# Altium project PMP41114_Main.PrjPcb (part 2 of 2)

## Sheet PMP41114_MAIN_LLC.SchDoc: LLC Power Stage
size A2; Date: Not shown in title block; ApprovedBy: Not shown in title block; CheckedBy: Not shown in title block; Author: Not shown in title block; CompanyName: Not shown in title block; DrawnBy: Desheng Guo; Engineer: Not shown in title block; Organization: Not shown in title block; Address1: Not shown in title block; Address2: Not shown in title block; Address3: Not shown in title block; Address4: Not shown in title block; DocumentNumber: 1; Revision: Use project parameter SCH_Rev; SheetNumber: 3; SheetTotal: 3; PageSetup: Record=PageOptions¦CenterHorizontal=True¦CenterVertical=True¦PrintScale=0.69¦XCorrection=1.00¦YCorrection=1.00¦PrintKind=0¦BorderSize=5000000¦LeftOffset=0¦BottomOffset=0¦Orientation=2¦PaperLength=1000¦PaperWidth=1000¦Scale=100¦PaperSource=15¦PrintQuality=600¦MediaType=1¦DitherType=10¦PaperKind=Letter¦PrintScaleMode=1
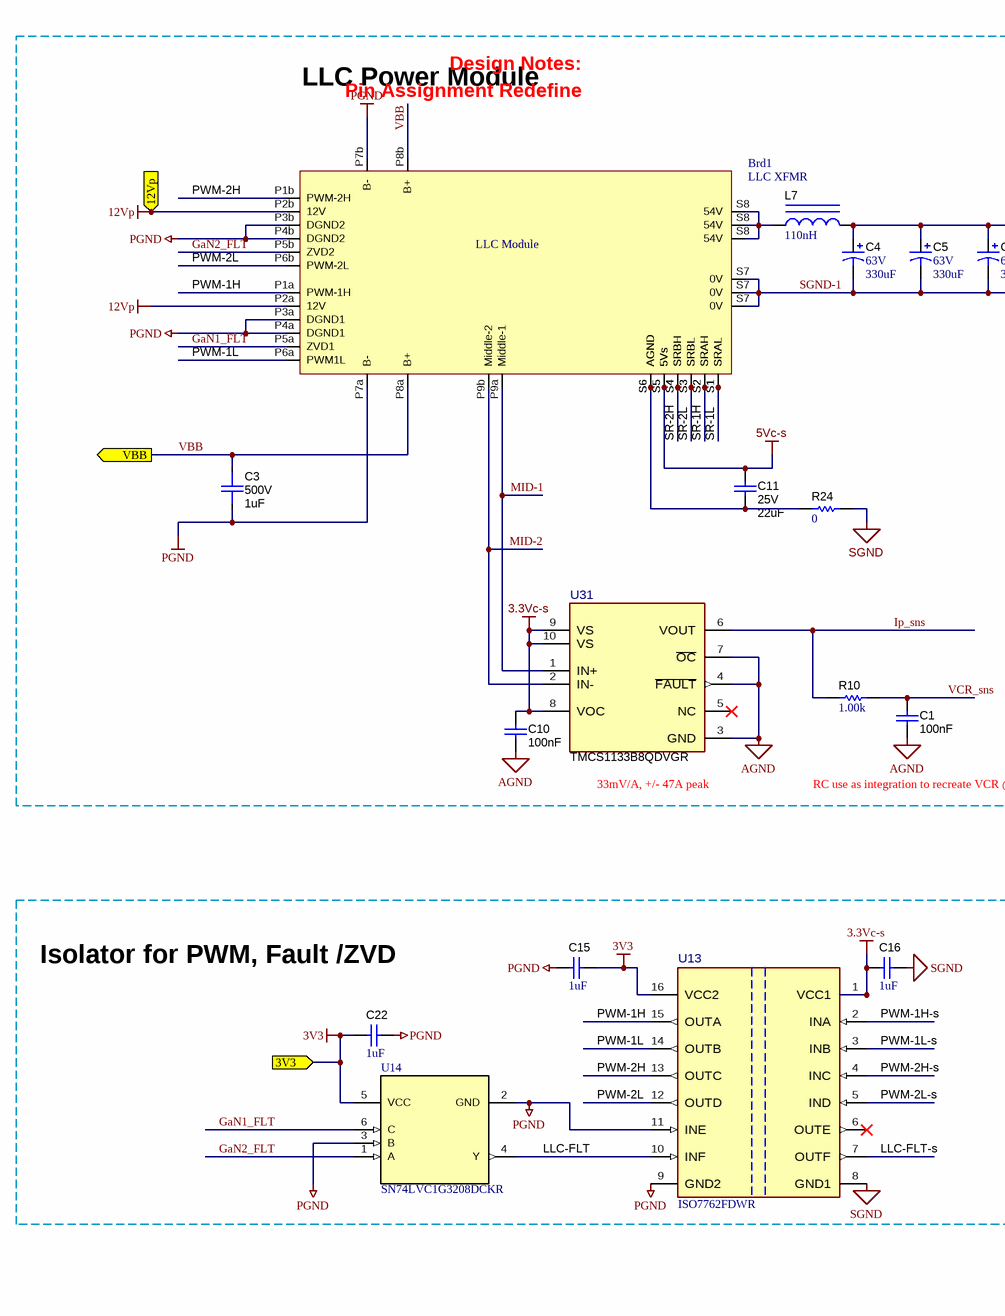
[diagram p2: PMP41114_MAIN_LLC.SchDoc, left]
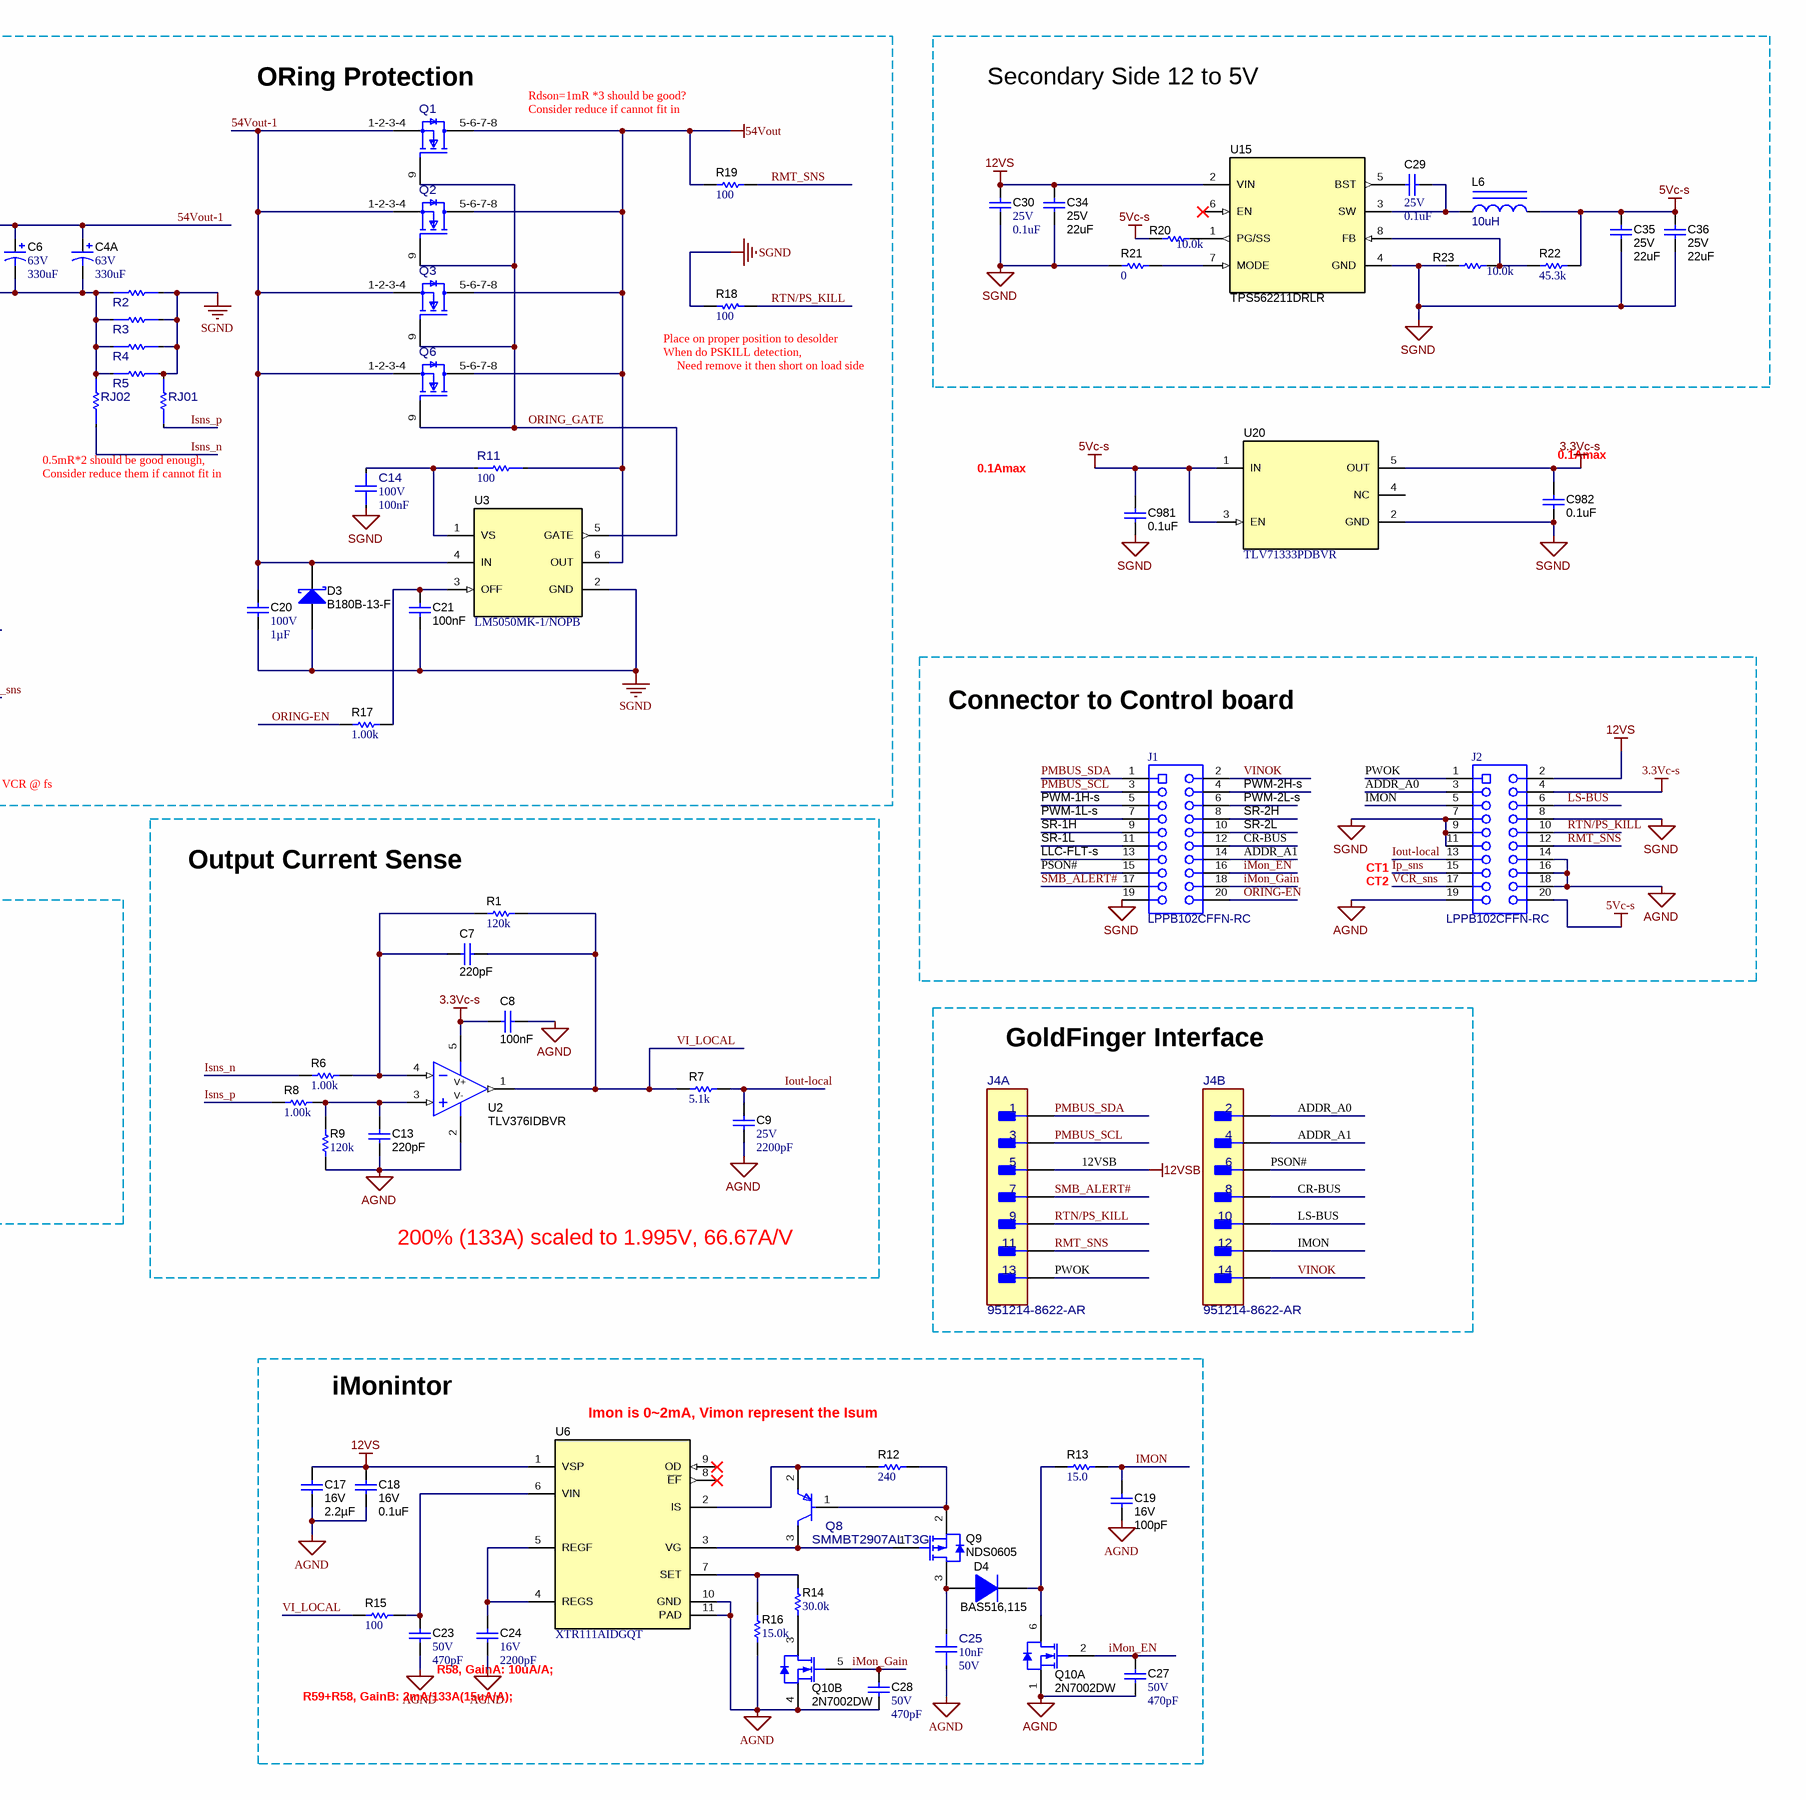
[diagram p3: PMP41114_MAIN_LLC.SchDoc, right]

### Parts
Brd1  LLC XFMR  [XFMR-PMP41114]
C1  Cap_F: 100nF  [0603]  (hidden comment: GRM188R71E104KA01D)
C3  VDC_V: 500V  ValueDisplayed: 1uF  [FP-B58031U5105M062_SMD2-MFG]  (hidden comment: B58031U5105M062)
C4  VDC_V: 63V  ValueDisplayed: 330uF  [KYB_1000x2500]  (hidden comment: EKYB630ELL331MJ25S)
C4A  VDC_V: 63V  ValueDisplayed: 330uF  [KYB_1000x2500]  (hidden comment: EKYB630ELL331MJ25S)
C5  VDC_V: 63V  ValueDisplayed: 330uF  [KYB_1000x2500]  (hidden comment: EKYB630ELL331MJ25S)
C6  VDC_V: 63V  ValueDisplayed: 330uF  [KYB_1000x2500]  (hidden comment: EKYB630ELL331MJ25S)
C7  ValueDisplayed: 220pF  [0603]  (hidden comment: GRM1885C1H221JA01D)
C8  Cap_F: 100nF  [0603]  (hidden comment: GRM188R71E104KA01D)
C9  VDC_V: 25V  ValueDisplayed: 2200pF  [0402]  (hidden comment: GRM155R71E222KA01D)
C10  Cap_F: 100nF  [0603]  (hidden comment: GRM188R71E104KA01D)
C11  VDC_V: 25V  ValueDisplayed: 22uF  [0805_HV]  (hidden comment: GRM21BR61E226ME44L)
C13  ValueDisplayed: 220pF  [0603]  (hidden comment: GRM1885C1H221JA01D)
C14  VDC_V: 100V  Cap_F: 100nF  [FP-885012206120_0603-MFG]  (hidden comment: 885012206120)
C15  ValueDisplayed: 1uF  [0402]  (hidden comment: GRM155R61A105KE15D)
C16  ValueDisplayed: 1uF  [0402]  (hidden comment: GRM155R61A105KE15D)
C17  VDC_V: 16V  Cap_F: 2.2µF  [0603]  (hidden comment: GRM188Z71C225KE43)
C18  VDC_V: 16V  ValueDisplayed: 0.1uF  [0402]  (hidden comment: GRM155R71C104KA88D)
C19  VDC_V: 16V  ValueDisplayed: 100pF  [0402]  (hidden comment: 0402YC101KAT2A)
C20  VDC_V: 100V  Cap_F: 1µF  [0805_150]  (hidden comment: KAF21KR72A105KU)
C21  Cap_F: 100nF  [0603]  (hidden comment: GRM188R71E104KA01D)
C22  ValueDisplayed: 1uF  [0402]  (hidden comment: GRM155R61A105KE15D)
C23  VDC_V: 50V  ValueDisplayed: 470pF  [0402]  (hidden comment: GRM155R71H471KA01D)
C24  VDC_V: 16V  ValueDisplayed: 2200pF  [0402]  (hidden comment: 885012205027)
C25  Cap_F: 10nF  VDC_V: 50V  [FP-C0603C103J5RAC7867_0603-MFG]  (hidden comment: C0603C103J5RAC7867)
C27  VDC_V: 50V  ValueDisplayed: 470pF  [0402]  (hidden comment: GRM155R71H471KA01D)
C28  VDC_V: 50V  ValueDisplayed: 470pF  [0402]  (hidden comment: GRM155R71H471KA01D)
C29  VDC_V: 25V  ValueDisplayed: 0.1uF  [0402]  (hidden comment: GRM155R71E104KE14D)
C30  VDC_V: 25V  ValueDisplayed: 0.1uF  [0402]  (hidden comment: GRM155R71E104KE14D)
C34  VDC_V: 25V  ValueDisplayed: 22uF  [0805_HV]  (hidden comment: GRM21BR61E226ME44L)
C35  VDC_V: 25V  ValueDisplayed: 22uF  [0805_HV]  (hidden comment: GRM21BR61E226ME44L)
C36  VDC_V: 25V  ValueDisplayed: 22uF  [0805_HV]  (hidden comment: GRM21BR61E226ME44L)
C981  ValueDisplayed: 0.1uF  [0402]  (hidden comment: GRM155R70J104KA01D)
C982  ValueDisplayed: 0.1uF  [0402]  (hidden comment: GRM155R70J104KA01D)
D3  B180B-13-F  [SMB]
D4  BAS516,115  [SOD-523]
J1  LPPB102CFFN-RC  [Sullins_LPPB102CFFN]
J2  LPPB102CFFN-RC  [Sullins_LPPB102CFFN]
J4  951214-8622-AR  [FP-951214-8622-AR_HDR14-MFG]  (parts A,B of 2)
L6  ValueDisplayed: 10uH  [VLS252010HBX]  (hidden comment: 74438323100)
L7  ValueDisplayed: 110nH  [SLC1480]  (hidden comment: SLC1480-111MLB)
Q1  IQD016N08NM5CGATMA1  [FP-IQD016N08NM5CGATMA1_TTFN-9-MFG]  (value not drawn)
Q2  IQD016N08NM5CGATMA1  [FP-IQD016N08NM5CGATMA1_TTFN-9-MFG]  (value not drawn)
Q3  IQD016N08NM5CGATMA1  [FP-IQD016N08NM5CGATMA1_TTFN-9-MFG]  (value not drawn)
Q6  IQD016N08NM5CGATMA1  [FP-IQD016N08NM5CGATMA1_TTFN-9-MFG]  (value not drawn)
Q8  SMMBT2907ALT3G  [FP-SMMBT2907ALT3G_SOT23-MFG]
Q9  NDS0605  [SOT-23]
Q10  2N7002DW  [SOT-363]  (parts A,B of 2)
R1  ValueDisplayed: 120k  [0402]  (hidden comment: CRCW0402120KFKED)
R2  CSS2H-2512R-L500F  [FP-CSS2H-2512R-L500F_2512-MFG]  (value not drawn)
R3  CSS2H-2512R-L500F  [FP-CSS2H-2512R-L500F_2512-MFG]  (value not drawn)
R4  CSS2H-2512R-L500F  [FP-CSS2H-2512R-L500F_2512-MFG]  (value not drawn)
R5  CSS2H-2512R-L500F  [FP-CSS2H-2512R-L500F_2512-MFG]  (value not drawn)
R6  ValueDisplayed: 1.00k  [0402]  (hidden comment: MCR01MZPF1001)
R7  ValueDisplayed: 5.1k  [0402]  (hidden comment: CRCW04025K10JNED)
R8  ValueDisplayed: 1.00k  [0402]  (hidden comment: MCR01MZPF1001)
R9  ValueDisplayed: 120k  [0402]  (hidden comment: CRCW0402120KFKED)
R10  ValueDisplayed: 1.00k  [0402]  (hidden comment: MCR01MZPF1001)
R11  value 100  [FP-RMCF0402FT100R_0402-MFG]  (hidden comment: RMCF0402FT100R)
R12  ValueDisplayed: 240  [0402]  (hidden comment: ERJ-2RKF2400X)
R13  ValueDisplayed: 15.0  [0402]  (hidden comment: CRCW040215R0FKED)
R14  ValueDisplayed: 30.0k  [0402]  (hidden comment: CRCW040230K0FKED)
R15  ValueDisplayed: 100  [0402]  (hidden comment: RC0402FR-07100RL)
R16  ValueDisplayed: 15.0k  [0402]  (hidden comment: RC0402FR-0715KL)
R17  ValueDisplayed: 1.00k  [0402]  (hidden comment: MCR01MZPF1001)
R18  ValueDisplayed: 100  [0402]  (hidden comment: RC0402FR-07100RL)
R19  ValueDisplayed: 100  [0402]  (hidden comment: RC0402FR-07100RL)
R20  ValueDisplayed: 10.0k  [0402]  (hidden comment: ERJ-2RKF1002X)
R21  ValueDisplayed: 0  [0402]  (hidden comment: RC0402JR-070RL)
R22  ValueDisplayed: 45.3k  [0402S]  (hidden comment: RC0402FR-0745K3L)
R23  ValueDisplayed: 10.0k  [0402]  (hidden comment: ERJ-2RKF1002X)
R24  ValueDisplayed: 0  [0402]  (hidden comment: RC0402JR-070RL)
RJ01  ERJ-2GE0R00X  [FP-ERJ-2GE0R00X_0402-MFG]  (value not drawn)
RJ02  ERJ-2GE0R00X  [FP-ERJ-2GE0R00X_0402-MFG]  (value not drawn)
U2  TLV376IDBVR  [DBV0005A_N]
U3  LM5050MK-1/NOPB  [DDC0006A_N]
U6  XTR111AIDGQT  [DGQ0010D_N]
U13  ISO7762FDWR  [DW0016B-MFG]
U14  SN74LVC1G3208DCKR  [DCK0006A_N]
U15  TPS562211DRLR  [DRL0008A]
U20  TLV71333PDBVR  [DBV0005A_N]
U31  TMCS1133B8QDVGR  [DVG0010A-MFG]

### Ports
3V3 (in), 12Vp (in), VBB (out)

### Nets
3.3Vc-s: C8.2 C10.1 C16.1 C982.1 J2.4 U2.5(V+) U13.1(VCC1) U20.5(OUT) U31.8(VOC) U31.9(VS) U31.10(VS)
3V3: C15.1 C22.1 U13.16(VCC2) U14.5(VCC) ; port 3V3
5Vc-s: Brd1.S5(5Vs) C11.1 C35.1 C36.1 C981.1 J2.20 L6.2 R20.2 R22.1 U20.1(IN) U20.3(EN)
12VP: Brd1.P2a(12V) Brd1.P2b(12V) ; port 12Vp
12VS: C17.1 C18.1 C30.2 C34.1 J2.2 U6.1(VSP) U15.2(VIN)
12VSB: J4.5
54Vout: Q1.5-6-7-8(Drain) Q2.5-6-7-8(Drain) Q3.5-6-7-8(Drain) Q6.5-6-7-8(Drain) R11.2 R19.1 U3.6(OUT)
AGND: C1.1 C8.1 C9.2 C10.2 C13.2 C17.2 C18.2 C19.2 C23.2 C24.2 C25.1 C27.2 C28.2 J2.14 J2.16 J2.18 J2.19 Q10.1(S) Q10.4(S) R9.1 R16.1 U2.2(V-) U6.10(GND) U6.11(PAD) U31.3(GND) U31.4(~{FAULT}) U31.7(~{OC})
PGND: Brd1.P3a(DGND1) Brd1.P3b(DGND2) Brd1.P4a(DGND1) Brd1.P4b(DGND2) Brd1.P7a(B-) Brd1.P7b(B-) C3.2 C15.2 C22.2 U13.9(GND2) U13.11(INE) U14.2(GND) U14.3(B)
SGND: C14.1 C16.2 C20.2 C21.2 C30.1 C34.2 C35.2 C36.2 C981.2 C982.2 D3.2(A) J1.19 J2.7 J2.8 J2.9 J2.11 R2.2 R3.2 R4.2 R5.2 R18.2 R21.1 R23.2 R24.1 RJ01.2 U3.2(GND) U13.8(GND1) U15.4(GND) U20.2(GND)
54Vout-1: C4.1(+) C4A.1(+) C5.1(+) C6.1(+) C20.1 D3.1(K) L7.2 Q1.1-2-3-4(Source) Q2.1-2-3-4(Source) Q3.1-2-3-4(Source) Q6.1-2-3-4(Source) U3.4(IN)
ADDR_A0: J2.3 J4.2
ADDR_A1: J1.14 J4.4
CR-BUS: J1.12 J4.8
GaN1_FLT: Brd1.P5a(ZVD1) U14.6(C)
GaN2_FLT: Brd1.P5b(ZVD2) U14.1(A)
IMON: C19.1 J2.5 J4.12 R13.2
iMon_EN: C27.1 J1.16 Q10.2(G)
iMon_Gain: C28.1 J1.18 Q10.5(G)
Iout-local: C9.1 J2.13 R7.2
Ip_sns: J2.15 R10.2 U31.6(VOUT)
Isns_n: R6.1 RJ02.1
Isns_p: R8.1 RJ01.1
LLC-FLT: U13.10(INF) U14.4(Y)
LLC-FLT-s: J1.13 U13.7(OUTF)
LS-BUS: J2.6 J4.10
MID-1: Brd1.P9a(Middle-1) U31.1(IN+)
MID-2: Brd1.P9b(Middle-2) U31.2(IN-)
ORING-EN: J1.20 R17.1
ORING_GATE: Q1.9(Gate) Q2.9(Gate) Q3.9(Gate) Q6.9(Gate) U3.5(GATE)
PMBUS_SCL: J1.3 J4.3
PMBUS_SDA: J1.1 J4.1
PSON#: J1.15 J4.6
PWM-1H: Brd1.P1a(PWM-1H) U13.15(OUTA)
PWM-1H-s: J1.5 U13.2(INA)
PWM-1L: Brd1.P6a(PWM1L) U13.14(OUTB)
PWM-1L-s: J1.7 U13.3(INB)
PWM-2H: Brd1.P1b(PWM-2H) U13.13(OUTC)
PWM-2H-s: J1.4 U13.4(INC)
PWM-2L: Brd1.P6b(PWM-2L) U13.12(OUTD)
PWM-2L-s: J1.6 U13.5(IND)
PWOK: J2.1 J4.13
RMT_SNS: J2.12 J4.11 R19.2
RTN/PS_KILL: J2.10 J4.9 R18.1
SGND-1: Brd1.S7(0V) C4.2(-) C4A.2(-) C5.2(-) C6.2(-) R2.1 R3.1 R4.1 R5.1 RJ02.2
SMB_ALERT#: J1.17 J4.7
SR-1H: Brd1.S2(SRAH) J1.9
SR-1L: Brd1.S1(SRAL) J1.11
SR-2H: Brd1.S4(SRBH) J1.8
SR-2L: Brd1.S3(SRBL) J1.10
VBB: Brd1.P8a(B+) Brd1.P8b(B+) C3.1 ; port VBB
VCR_sns: C1.2 J2.17 R10.1
VI_LOCAL: C7.2 R1.1 R7.1 R15.1 U2.1(OUT)
VINOK: J1.2 J4.14
NetBrd1_S6: Brd1.S6(AGND) C11.2 R24.2
NetBrd1_S8: Brd1.S8(54V) L7.1
NetC7_1: C7.1 R1.2 R6.2 U2.4(IN-)
NetC13_1: C13.1 R8.2 R9.2 U2.3(IN+)
NetC14_2: C14.2 R11.1 U3.1(VS)
NetC21_1: C21.1 R17.2 U3.3(OFF)
NetC23_1: C23.1 R15.2 U6.6(VIN)
NetC24_1: C24.1 U6.4(REGS) U6.5(REGF)
NetC25_2: C25.2 D4.2(A) Q9.3(D)
NetC29_1: C29.1 U15.5(BST)
NetC29_2: C29.2 L6.1 U15.3(SW)
NetD4_1: D4.1(K) Q10.6(D) R13.1
NetQ8_1: Q8.1(BASE) Q9.2(S) R12.2
NetQ8_2: Q8.2(EMITTER) R12.1 U6.2(IS)
NetQ8_3: Q8.3(COLLECTOR) Q9.1(G) U6.3(VG)
NetQ10_3: Q10.3(D) R14.1
NetR14_2: R14.2 R16.2 U6.7(SET)
NetR20_1: R20.1 U15.1(PG/SS)
NetR21_2: R21.2 U15.7(MODE)
NetR22_2: R22.2 R23.1 U15.8(FB)

Not connected (* = marked no-connect by the designer): U6 8(~{EF})* 9(OD)*; U13 6(OUTE)*; U15 6(EN)*; U20 4(NC); U31 5(NC)*

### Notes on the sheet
- LLC Power Module
- Design Notes:
- Pin Assignment Redefine
- (near Q1) ORing Protection
- Secondary Side 12 to 5V
- 0.1Amax
- 0.5mR*2 should be good enough,
- Consider reduce them if cannot fit in
- Connector to Control board
- (near U31) 33mV/A, +/- 47A peak
- RC use as integration to recreate VCR @ fs
- (near R1) Output Current Sense
- CT1
- CT2
- Isolator for PWM, Fault /ZVD
- GoldFinger Interface
- 200% (133A) scaled to 1.995V, 66.67A/V
- iMonintor
- Imon is 0|mA, Vimon represent the Isum
- R58, GainA: 10uA/A;
- R59+R58, GainB: 2mA/133A(15uA/A);
- Labels drawn without touching a wire or pin: Consider reduce if cannot fit in, Need remove it then short on load side, Place on proper position to desolder, Rdson=1mR *3 should be good?, When do PSKILL detection,

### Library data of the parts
Brd1 = PMP41114_LLC_MODULE: 3.6kW 400V to 54V FB LLC Module
C1 C8 C10 C21 = CMP-0007404-4: CAP, CERM, 0.1 uF, 25 V, +/- 10%, X7R, 0603; Manufacturer: MuRata; TaMin_C: -55°C; Polarized: N; SizeAreaWB_mm2: 4.68; Value1: Unknown; U/M: EA; Value: 0.1uF; TaMax_C: 125°C; SizeZ_mm: 1; SizeX_mm: 1.6; SizeY_mm: 0.8; Value2: 25V; SizeArea_mm2: 1.28; CompType: Capacitor; AEC Category: Q200
C3 = CMP-0091050-1: TDK 1µF Multilayer Ceramic Capacitor MLCC 500V dc ±20% SMD; AEC Grade: Grade 0; AEC Qualified: Yes; SizeZ_mm: 4.5mm
C4 C4A C5 C6 = CMP-0009877-2: CAP, AL, 330 uF, 63 V, +/- 20%, 0.045 ohm, TH; Manufacturer: Chemi-Con; TaMin_C: -40°C; ESR_ohm: 0.045; Polarized: Y; SizeAreaWB_mm2: 144; U/M: EA; Value: 330uF; TaMax_C: 105°C; SizeZ_mm: 26.5; SizeX_mm: 10; Cap_Case: 10x25mm; SizeArea_mm2: 100; CompType: Capacitor; Cap_F: 330µF; IRMS_A: 1.55A; AEC Category: Q200
C7 C13 = CMP-0007197-4: CAP, CERM, 220 pF, 50 V, +/- 5%, C0G/NP0, 0603; Manufacturer: MuRata; TaMin_C: -55°C; Polarized: N; SizeAreaWB_mm2: 4.68; Value1: Unknown; U/M: EA; Value: 220pF; TaMax_C: 125°C; SizeZ_mm: 1; SizeX_mm: 1.6; SizeY_mm: 0.8; Value2: 50V; SizeArea_mm2: 1.28; CompType: Capacitor; AEC Category: Q200
C9 = CMP-0006663-2: CAP, CERM, 2200 pF, 25 V, +/- 10%, X7R, 0402; Manufacturer: MuRata; TaMin_C: -55°C; Polarized: N; SizeAreaWB_mm2: 3; Value1: Unknown; U/M: EA; Value: 2200pF; TaMax_C: 125°C; SizeZ_mm: 0.6; SizeX_mm: 1; SizeY_mm: 0.5; Cap_F: 2.2nF; AEC Category: Q200
C11 C34-C36 = CMP-0008305-2: CAP, CERM, 22 uF, 25 V, +/- 20%, X5R, 0805; Manufacturer: MuRata; TaMin_C: -55°C; Polarized: N; SizeAreaWB_mm2: 6.75; Value1: Unknown; U/M: EA; Value: 22uF; TaMax_C: 85°C; SizeZ_mm: 1.45; SizeX_mm: 2; SizeY_mm: 1.25; Cap_Case: 0805; SizeArea_mm2: 2.5; Cap_F: 22µF; AEC Category: Q200
C14 = CMP-0097294-1: 0.1 µF ±10% 100V Ceramic Capacitor X7R 0603 (1608 Metric); Manufacturer: Wurth Electronics; TempCo: 15%; SizeZ_mm: 0.87mm; Value: 100nF; AEC Qualified: No
C15 C16 C22 = CMP-0006563-2: CAP, CERM, 1 uF, 10 V, +/- 10%, X5R, 0402; Manufacturer: MuRata; Polarized: N; Value: 1uF; U/M: EA; Cap_F: 1µF; Value1: Unknown; VDC_V: 10V; TaMin_C: -55°C; TaMax_C: 85°C; SizeArea_mm2: 0.5; SizeAreaWB_mm2: 3; SizeX_mm: 1; SizeZ_mm: 0.6; AEC Category: Q200
C17 = CMP-0007499-4: CAP, CERM, 2.2 uF, 16 V, +/- 10%, X7R, 0603; Manufacturer: MuRata; TaMin_C: -55°C; Polarized: N; SizeAreaWB_mm2: 4.68; Value1: Unknown; U/M: EA; Value: 2.2uF; TaMax_C: 125°C; SizeZ_mm: 1; SizeX_mm: 1.6; SizeY_mm: 0.8; SizeArea_mm2: 1.28; AEC Category: Q200
C18 = CMP-0006641-2: CAP, CERM, 0.1 uF, 16 V, +/- 10%, X7R, 0402; Manufacturer: MuRata; TaMin_C: -55°C; Polarized: N; SizeAreaWB_mm2: 3; Value1: Unknown; U/M: EA; Value: 0.1uF; TaMax_C: 125°C; SizeZ_mm: 0.6; SizeX_mm: 1; SizeY_mm: 0.5; Cap_F: 100nF; AEC Category: Q200
C19 = CMP-0006200-2: CAP, CERM, 100 pF, 16 V, +/- 10%, X7R, 0402; Manufacturer: AVX; TaMin_C: -55°C; Polarized: N; SizeAreaWB_mm2: 3; Value1: Unknown; U/M: EA; Value: 100pF; TaMax_C: 125°C; SizeZ_mm: 0.6; SizeX_mm: 1; SizeY_mm: 0.5; AEC Category: Q200
C20 = CMP-0861070-2: CAP, CERM, 1 µF, 100 V,+/- 10%, X7R, AEC-Q200 Grade 1, 0805; Manufacturer: AVX; SizeZ_mm: 1.5; Polarized: N; TaMax_C: 125°C; TaMin_C: -55°C; Value: 1uF; AEC Qualified: Y; U/M: EA; AEC Grade: 1; Cap_Case: 0805; SizeX_mm: 2; SizeArea_mm2: 2.5; SizeAreaWB_mm2: 6.75; AEC Category: Q200; SizeY_mm: 1.25
C23 C27 C28 = CMP-0006691-2: CAP, CERM, 470 pF, 50 V, +/- 10%, X7R, 0402; Manufacturer: MuRata; TaMin_C: -55°C; Polarized: N; SizeAreaWB_mm2: 3; Value1: Unknown; U/M: EA; Value: 470pF; TaMax_C: 125°C; SizeZ_mm: 0.6; SizeX_mm: 1; SizeY_mm: 0.5; AEC Category: Q200
C24 = CMP-0006225-2: CAP, CERM, 2200 pF, 16 V, +/- 10%, X7R, 0402; Manufacturer: Wurth Elektronik; TaMin_C: -55°C; Polarized: N; SizeAreaWB_mm2: 3; Value1: Unknown; U/M: EA; Value: 2200pF; TaMax_C: 125°C; SizeZ_mm: 0.6; SizeX_mm: 1; SizeY_mm: 0.5; Cap_F: 2.2nF; AEC Category: Q200
C25 = CMP-0120172-1: 10000 pF ±5% 50V Ceramic Capacitor X7R 0603 (1608 Metric); Manufacturer: KEMET; AEC Qualified: No; SizeZ_mm: 0.9mm; TempCo: 15%; ValueDisplayed: 0.01uF; Value: 10nF
C29 C30 = CMP-0006659-2: CAP, CERM, 0.1 uF, 25 V, +/- 10%, X7R, 0402; Manufacturer: MuRata; TaMin_C: -55°C; Polarized: N; SizeAreaWB_mm2: 3; Value1: Unknown; U/M: EA; Value: 0.1uF; TaMax_C: 125°C; SizeZ_mm: 0.6; SizeX_mm: 1; SizeY_mm: 0.5; Cap_F: 100nF; AEC Category: Q200
C981 C982 = CMP-0006623-2: CAP, CERM, 0.1 uF, 6.3 V, +/- 10%, X7R, 0402; Manufacturer: MuRata; Polarized: N; Value: 0.1uF; U/M: EA; Cap_F: 100nF; Value1: Unknown; VDC_V: 6.3V; TaMin_C: -55°C; TaMax_C: 125°C; AEC Category: Q200; SizeArea_mm2: 0.5; SizeAreaWB_mm2: 3; SizeX_mm: 1; SizeZ_mm: 0.6
D3 = CMP-0028394-2: Diode, Schottky, 80 V, 1 A, SMB; Manufacturer: Diodes Inc.; Value2: 0.79V; Value1: 1A; TJmax_C: 150°C; SizeY_mm: 3.81; SizeX_mm: 5.6; Green_REACh: Incomplete; Value: 80V; SizeZ_mm: 2.6; SizeArea_mm2: 21.336; Vf_V: 790mV; RJC_CperW: 25; Green_Lifecycle: Not Set; SizeAreaWB_mm2: 44.156; AEC Category: Q101
D4 = CMP-0076979-3: Diode, Switching, 100 V, 0.25 A, SOD-523; Manufacturer: Nexperia; Value: 100V; SizeAreaWB_mm2: 5.13; Vf_V: 1.25V; SizeArea_mm2: 1.53; SizeY_mm: 0.9; Green_Lifecycle: Not Set; AEC Category: Q101; SizeX_mm: 1.7; Green_REACh: Incomplete; Io_A: 250mA; TJmax_C: 150°C; SizeZ_mm: 0.65; Value1: 0.25A
J1 J2 = CMP-0750171-1: Receptacle, 1.27mm, 10x2, Gold, TH; Manufacturer: Sullins Connector Solutions; Gender: Female; Current_A: 1A; Cert_UL: Y; Row_Count: 2; Pitch_mm: 1.27
J4 = CMP-0089162-1: Connector Header Through Hole 14 position 0.079" (2.00mm); Manufacturer: 3M; Conn Orientation: Straight; ContactFinish: Gold,Nickel; Current_A: 2A; AEC Qualified: No; DUT-Pitch_mm: 2mm; Conn Gender: Male; SizeZ_mm: 6.3mm; Row_Count: 2
L6 = CMP-0063086-1: Inductor, Wirewound, Ferrite, 10 uH, 0.68 A, 0.46 ohm, SMD; Manufacturer: Würth Elektronik; Isat: 1.35A @ 20% inductance drop; Irms: 0.60A @ 40C rise; Green_Lifecycle: Active; SizeAreaWB_mm2: 10.5; DCR_ohm: 0.46; Green_REACh: Passed; Value1: 0.843 ohm; Value: 10uH; Imax_A: 600mA; SizeZ_mm: 1; SizeX_mm: 2.5; SizeY_mm: 2; Value2: 0.6A; SizeArea_mm2: 5; Ind_H: 10µH; AEC Qualified: N; AEC Category: Q200
L7 = CMP-0060882-1: Inductor, Shielded, Ferrite, 110 nH, 55 A, 0.00015 ohm, SMD; Manufacturer: Coilcraft; Isat: 130A @ 30% inductance drop; Irms: 55A @ 40C rise; Green_Lifecycle: Not Set; SizeAreaWB_mm2: 231.127; DCR_ohm: 150µ; Green_REACh: Incomplete; Value: 110nH; Imax_A: 55A; SizeZ_mm: 8; SizeX_mm: 13.46; SizeY_mm: 12.95; SizeArea_mm2: 174.307; AEC Category: Q200
Q1-Q3 Q6 = CMP-0122332-1: N-Channel 80 V 31A (Ta), 323A (Tc) 3W (Ta), 333W (Tc) Surface Mount PG-TTFN-9-U02; Manufacturer: Infineon; AEC Qualified: No; QgTyp_nC: 106nC @ 10V; Rdson45_ohm: 1.4m; SizeZ_mm: 1.1mm; VdsMax_V: 1V; Vgs_V: 20V; ChMode: False; Drain To Source Breakdown Voltage: 80V; Input Capacitace At Vds: 7100pF @ 40V; Number Of Channels: 1; Pulse Drain Current: 1292A; Reverse Recovery Charge: 71nC; Reverse Recovery Time: 48ns; Rthja Max: 50°C/W; Threshold Vgs Max: 3.8V; Threshold Vgs Min: 2.2V; TJmax_C: +175°C; Transconductance: 140S; Turn Off Delay Time: 29ns; Turn On Delay Time: 15ns; Typ Forward Diode Voltage: 0.82V
Q8 = CMP-0097439-1: Bipolar (BJT) Transistor PNP 60 V 600 mA 200MHz 300 mW Surface Mount SOT-23-3 (TO-236); Manufacturer: On Semiconductor; Delay Time Td: 10ns; Power_W: 225mW; Number Of Elements: 1; AEC Qualified: Yes; Rise Time Tr: 40ns; HfeMax: 300; AEC Grade: Grade 0; SizeZ_mm: 1.11mm; Collector Base Voltage: -60V; Fall Time Tf: 30ns; Emitter Base Voltage: -5V; Hfe Testic: -150mA; Hfe Min: 100; Hfe Testvce: -10V; Standoff Height: 0.01mm; IcRated_A: -600mA; Vcesat1_V: -1.6V; Value: -60V; TJmax_C: +150°C; Import Ts: 1521847999; Rthja Max: 556°C/W; Ciiva Ids: 860677
Q9 = CMP-0083635-2: MOSFET, P-CH, -60 V, -0.18 A, SOT-23; Manufacturer: Fairchild Semiconductor; Alternate Manufacturer: None; ChMode: Enhancement; Value: -60V; Green_REACh: Incomplete; Value2: 1.8 nC; AEC Qualified: N; Green_Lifecycle: Active; QgTyp_nC: 1.8; SizeArea_mm2: 7.5; ChType: P; SizeAreaWB_mm2: 14; SizeY_mm: 3; AEC Category: Q101; SizeX_mm: 2.5; Vgs_V: 20V; SizeZ_mm: 1.1; Value1: 7.5 ohm; IdsMax_A: -180mA
Q10 = CMP-0000770-1: MOSFET, 2-CH, N-CH, 60 V, 0.115 A, SOT-363; Alternate Manufacturer: None; Manufacturer: Fairchild Semiconductor; SizeZ_mm: 1.1; ChType: N; VdsMax_V: 60V; SizeX_mm: 2.2; Vgs_V: 20V; Value: 60V; SizeArea_mm2: 4.84; AEC Category: Q101; IdsMax_A: 1.15dA; SizeAreaWB_mm2: 10.24; U/M: EA
R1 R9 = CMP-0025983-3: RES, 120 k, 1%, 0.063 W, AEC-Q200 Grade 0, 0402; Manufacturer: Vishay-Dale; Power_W: 63mW; TempCo: 100 ppm/C; Value: 120k; SizeX_mm: 1; SizeY_mm: 0.5; SizeZ_mm: 0.6; Value2: 0.063W; AEC Qualified: Y; VDC_V: 50V; AEC Category: Q200; AEC Grade: 0
R2-R5 = CMP-0095938-1: 500 µOhms ±1% 6W Chip Resistor 2512 (6432 Metric) Automotive AEC-Q200, Current Sense Metal Element; Manufacturer: Bourns; AEC Qualified: Yes; Standoff Height: 0.15mm; SizeZ_mm: 1.23mm; Value: 500µ; TempCo: 100ppm/°C; AEC Grade: Grade 0
R6 R8 R10 R17 = CMP-0026716-1: RES, 1.00 k, 1%, 0.063 W, 0402; Manufacturer: Rohm; Power_W: 63mW; TempCo: 100 ppm/C; Value_Code: 1k00; U/M: EA; Value: 1.00k; EIA_Code: E96; Res_ohm: 1k; SizeX_mm: 1; SizeY_mm: 0.5; SizeZ_mm: 0.6; Value2: 0.063W; AEC Qualified: N; VDC_V: 50V; AEC Category: Q200
R7 = CMP-0026951-5: RES, 5.1 k, 5%, 0.063 W, AEC-Q200 Grade 0, 0402; Manufacturer: Vishay-Dale; Power_W: 63mW; TempCo: 200 ppm/C; Value_Code: 5k10; Value: 5.1k; EIA_Code: E24; SizeX_mm: 1; SizeY_mm: 0.5; SizeZ_mm: 0.6; Value2: 0.063W; AEC Qualified: Y; VDC_V: 50V; AEC Category: Q200; AEC Grade: 0
R11 = CMP-0094733-1: 100Ω ±1% 0.063W 0402 Thick Film Chip Resistor AEC-Q200 compliant; Manufacturer: Stackpole Electronics; AEC Grade: Grade 0; Power_W: 63mW; TempCo: 100ppm/°C; VDC_V: 50V; SizeZ_mm: 0.35mm; AEC Qualified: Yes
R12 = CMP-0026684-1: RES, 240, 1%, 0.1 W, AEC-Q200 Grade 0, 0402; Manufacturer: Panasonic; Power_W: 100mW; TempCo: 100 ppm/C; Value_Code: 240R; U/M: EA; Value: 240; SizeX_mm: 1; SizeY_mm: 0.5; SizeZ_mm: 0.6; Value2: 0.1W; AEC Qualified: Y; VDC_V: 50V; AEC Grade: 0; AEC Category: Q200
R13 = CMP-0026030-3: RES, 15.0, 1%, 0.063 W, AEC-Q200 Grade 0, 0402; Manufacturer: Vishay-Dale; Power_W: 63mW; TempCo: 100 ppm/C; Value_Code: 15R0; Value: 15.0; EIA_Code: E96; Res_ohm: 15; SizeX_mm: 1; SizeY_mm: 0.5; SizeZ_mm: 0.6; Value2: 0.063W; AEC Qualified: Y; VDC_V: 50V; AEC Category: Q200; AEC Grade: 0
R14 = CMP-0078244-2: RES, 30.0 k, 1%, 0.063 W, AEC-Q200 Grade 0, 0402; Manufacturer: Vishay-Dale; Power_W: 63mW; Green_Lifecycle: Active; TempCo: 100 ppm/C; Value_Code: 30k0; Green_REACh: Passed; Value: 30.0k; Res_ohm: 30k; SizeX_mm: 1; SizeY_mm: 0.5; SizeZ_mm: 0.6; Value2: 0.063W; AEC Qualified: Y; VDC_V: 50V; AEC Grade: 0; AEC Category: Q200
R15 R18 R19 = CMP-0026722-1: RES, 100, 1%, 0.063 W, 0402; Manufacturer: Yageo America; Power_W: 63mW; TempCo: 100 ppm/C; Value_Code: 100R; U/M: EA; Value: 100; EIA_Code: E96; SizeX_mm: 1; SizeY_mm: 0.5; SizeZ_mm: 0.6; Value2: 0.063W; AEC Qualified: N; VDC_V: 50V; AEC Category: Q200
R16 = CMP-0078583-1: RES, 15.0 k, 1%, 0.063 W, 0402; Manufacturer: Yageo America; Power_W: 63mW; Green_Lifecycle: Active; TempCo: 100 ppm/C; Value_Code: 15k0; Green_REACh: Passed; Value: 15.0k; EIA_Code: E96; Res_ohm: 15k; SizeX_mm: 1; SizeY_mm: 0.5; SizeZ_mm: 0.6; Value2: 0.063W; AEC Qualified: N; AEC Category: Q200
R20 R23 = CMP-0026658-1: RES, 10.0 k, 1%, 0.1 W, 0402; Manufacturer: Panasonic; Value: 10.0k; Power_W: 100mW; TempCo: 100 ppm/C; Value_Code: 10k0; U/M: EA; EIA_Code: E96; Res_ohm: 10k; SizeX_mm: 1; SizeY_mm: 0.5; SizeZ_mm: 0.6; Value2: 0.1W; VDC_V: 50V; AEC Category: Q200
R21 R24 = CMP-0027004-2: RES, 0, 5%, 0.063 W, 0402; Manufacturer: Yageo America; Power_W: 63mW; TempCo: 200 ppm/C; Value_Code: 0000; U/M: EA; Value: 0; EIA_Code: E24; SizeX_mm: 1; SizeY_mm: 0.5; SizeZ_mm: 0.6; Value2: 0.063W; VDC_V: 50V; AEC Category: Q200
R22 = CMP-0077552-1: RES, 45.3 k, 1%, 0.063 W, 0402; Manufacturer: Yageo America; Value_Code: 45k3; SizeArea_mm2: 0.5; AEC Qualified: N; AEC Category: Q200; Value: 45.3k; SizeZ_mm: 0.6; EIA_Code: E96; TempCo: 100 ppm/C; Power_W: 63mW; VDC_V: 50V; Value2: 0.063W; U/M: EA; SizeX_mm: 1.0
RJ01 RJ02 = CMP-0002710-1: 0 Ohms Jumper Chip Resistor 0402 (1005 Metric) Automotive AEC-Q200 Thick Film; Manufacturer: Panasonic; AEC Grade: Grade 0; AEC Qualified: Yes; Res_ohm: 0; SizeZ_mm: 0.4mm; Power: 100mW; Value: 0
U2 = CMP-0073542-1: TLVx376, 5.5 MHz, Low-Noise, Low Quiescent Current, Precision Operational Amplifiers, DBV0005A (SOT-23-5); Alternate PartNumber: TLV376IDBVT; Alternate Manufacturer: Texas Instruments; SizeAreaWB_mm2: 14.82; U/M: EA; SizeZ_mm: 1.45; SizeX_mm: 2.8; SizeY_mm: 2.9; SizeArea_mm2: 8.12; CompType: IC
U3 = CMP-0066129-2: High Side OR-ing FET Controller, DDC0006A (SOT-23-T-6); Manufacturer: Texas Instruments; SizeZ_mm: 0.87; SizeX_mm: 1.65; SizeY_mm: 2.95; SizeArea_mm2: 4.8675; CompType: IC; U/M: EA; SizeAreaWB_mm2: 10.4675
U6 = CMP-0074287-2: Precision Voltage-to-Current Converter/Transmitter, DGQ0010D (VSSOP-10); Alternate Manufacturer: Texas Instruments; SizeAreaWB_mm2: 23.6; U/M: EA; SizeZ_mm: 1.1; SizeX_mm: 4.9; SizeY_mm: 3.0; SizeArea_mm2: 14.7; CompType: IC; AEC Category: Q200; AEC Qualified: N
U13 = CMP-0092396-1: General Purpose Digital Isolator 5000Vrms 6 Channel 100Mbps 85kV/µs CMTI 16-SOIC (0.295", 7.50mm Width); Manufacturer: Texas Instruments; TaMin_C: -55°C; TaMax_C: +125°C; Nominal Supply Current: 2.1-25.7mA; SizeZ_mm: 2.65mm; AEC Qualified: No; Max Supply Voltage: 5.5V; Min Supply Voltage: 2.25V; Standoff Height: 0.1mm; Interface: SPI,CAN; TJmax_C: +150°C
U14 = CMP-0051004-3: Single 3-Input Positive OR-AND Gate, DCK0006A (SOT-SC70-6); Manufacturer: Texas Instruments; Output Type: CMOS; Bits(#): 1; Input Type: CMOS/TTL; Technology Family: LVC; Schmitt Trigger: No; VCC(Max)(V): 5.5; Gate Type: Configurable; Rating: Catalog; Output Drive (IOL/IOH)(Max)(mA): 32/-32; ICC @ Nom Voltage(Max)(mA): 0.01; VCC(Min)(V): 1.65; F @ Nom Voltage(Max)(Mhz): 150; Logic: True; Voltage(Nom)(V): 1.8,2.5,3.3,5; tpd @ Nom Voltage(Max)(ns): 17.5,7.5,5.9,4.5; AEC Category: Q200; AEC Qualified: N; CompType: IC; SizeAreaWB_mm2: 9.3; SizeArea_mm2: 4.2; SizeX_mm: 2.1; SizeY_mm: 2.0; SizeZ_mm: 1.1
U15 = CMP-0861057-2: 4.2-V to 17-V Input, 2-A Synchronous Buck Converter, DRL0008A (SOT-5X3-8); Alternate Manufacturer: Texas Instruments; AEC Category: Q200; SizeX_mm: 1.6; SizeY_mm: 2.1; CompType: IC; SizeZ_mm: 0.6; SizeAreaWB_mm2: 8.06; AEC Qualified: N; SizeArea_mm2: 3.36
U20 = CMP-0066771-1: 150-mA, Low-Dropout Regulator with Foldback Current Limit for Portable Devices, DBV0005A (SOT-23-5); Alternate PartNumber: TLV71333PDBVT; Alternate Manufacturer: Texas Instruments; Green_Lifecycle: Active; SizeAreaWB_mm2: 14.82; Green_REACh: Passed; U/M: EA; SizeZ_mm: 1.45; SizeX_mm: 2.8; SizeY_mm: 2.9; SizeArea_mm2: 8.12; CompType: IC
U31 = CMP-0097985-1: Manufacturer: Texas Instruments; Part Number: TMCS1133B2QDVGR; SizeZ_mm: 2.65mm; Standoff Height: 0.1mm

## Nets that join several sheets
3V3: PMP41114_MAIN_PFC (C62.1 R83.2 U10.5), PMP41114_MAIN_PFC_Control (C26.1 J22M.6 U4.5), PMP41114_MAIN_LLC (C15.1 C22.1 U13.16 U14.5)
12VP: PMP41114_MAIN_PFC (9 pins), PMP41114_MAIN_PFC_Control (J21A.20), PMP41114_MAIN_LLC (Brd1.P2a Brd1.P2b)
12Vp_h: PMP41114_MAIN_PFC (C67.2 C74.1 U11.11 U11.16), PMP41114_MAIN_PFC_Control (J21A.8)
12VS: PMP41114_MAIN_PFC_Control (J22A.2), PMP41114_MAIN_LLC (7 pins)
12VSB: PMP41114_MAIN_PFC_Control (J22A.3 J22A.4 J22A.6), PMP41114_MAIN_LLC (J4.5)
PGND: PMP41114_MAIN_PFC (33 pins), PMP41114_MAIN_PFC_Control (21 pins), PMP41114_MAIN_LLC (13 pins)
SGND: PMP41114_MAIN_PFC_Control (J22A.5 J22A.7 J22A.8), PMP41114_MAIN_LLC (29 pins)
2V5ref: PMP41114_MAIN_PFC (R86.2), PMP41114_MAIN_PFC_Control (C32.2 U5.5)
5Vp: PMP41114_MAIN_PFC (12 pins), PMP41114_MAIN_PFC_Control (C31.2 U1.5 U5.3 U5.4)
AC_CUR_SENSE: PMP41114_MAIN_PFC (U7.7), PMP41114_MAIN_PFC_Control (J21M.13)
ACL_SENSE: PMP41114_MAIN_PFC (R62.1), PMP41114_MAIN_PFC_Control (J21M.19)
ACN_SENSE: PMP41114_MAIN_PFC (R87.1), PMP41114_MAIN_PFC_Control (J21M.9)
BB_ONOFF: PMP41114_MAIN_PFC (C69.1 U11.2), PMP41114_MAIN_PFC_Control (J22M.3)
BBFET: PMP41114_MAIN_PFC (R88.1), PMP41114_MAIN_PFC_Control (J22M.5)
LFFET_HS: PMP41114_MAIN_PFC (C64.1 U9.2), PMP41114_MAIN_PFC_Control (J21M.20)
LFFET_LS: PMP41114_MAIN_PFC (C65.1 U9.1), PMP41114_MAIN_PFC_Control (J21M.18)
RELAY_CTRL: PMP41114_MAIN_PFC (C68.1 U11.1), PMP41114_MAIN_PFC_Control (J22M.1)
VBB: PMP41114_MAIN_PFC (C2.2 D11.2 Q5.9), PMP41114_MAIN_PFC_Control (J21A.1 J21A.2 R50.2), PMP41114_MAIN_LLC (Brd1.P8a Brd1.P8b C3.1)
Vbulk: PMP41114_MAIN_PFC (18 pins), PMP41114_MAIN_PFC_Control (R47.2)
ZCD: PMP41114_MAIN_PFC (9 pins), PMP41114_MAIN_PFC_Control (R43.1)

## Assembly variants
001: not fitted FID1 FID2 FID3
